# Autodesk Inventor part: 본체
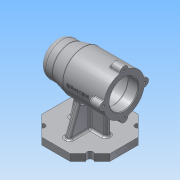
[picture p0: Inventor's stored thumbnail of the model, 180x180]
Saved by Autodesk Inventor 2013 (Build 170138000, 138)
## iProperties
Created: 2021-01
Part Number: 본체
Material: 알루미늄 6061
Document SubType Name: Modeling
Designer: Administrator
Density: 2.71 g/cm^3
Mass: 632.297 g
Surface Area: 613.785 cm^2
Volume: 233.32 cm^3
Author: Administrator
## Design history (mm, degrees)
sketch "스케치1" dims "d0" = 100
  geometry: L1 (20.711, 50)-(50, 20.711); L2 (50, 20.711)-(50, -20.711); L3 (50, -20.711)-(20.711, -50); L4 (20.711, -50)-(-20.711, -50); L5 (-20.711, -50)-(-50, -20.711); L6 (-50, -20.711)-(-50, 20.711); L7 (-50, 20.711)-(-20.711, 50); L8 (-20.711, 50)-(20.711, 50); 4 further points
  constraints: 16 end point, 2 coincident, 2 vertical alignment, 1 midpoint, 19 other
extrude "돌출1" new body sketch "스케치1" distance "d2" = 10; taper "d3" = 0 deg
sketch "스케치2"
  geometry: L1 (-50, -10)-(-20.711, -10) reference; L2 (20.711, 0)-(50, 0) reference; L3 (50, 65)-(-50, 65); L4 (-50, 65)-(-50, 90); L5 (-50, 90)-(-30, 90); L6 (-30, 90)-(-10, 95); L7 (-10, 95)-(50, 95); L8 (50, 95)-(50, 86); L9 (50, 86)-(35, 86); L10 (35, 86)-(35, 89); L11 (35, 89)-(-7, 89); L12 (-7, 89)-(-7, 86); L13 (-7, 86)-(-19, 86); L14 (-19, 86)-(-19, 82.5); L15 (-19, 82.5)-(-37, 82.5); L16 (-37, 82.5)-(-37, 81); L17 (-37, 81)-(-41, 81); L18 (-41, 81)-(-41, 75.5); L19 (-41, 75.5)-(-44, 75.5); L20 (-44, 75.5)-(-44, 65); 1 further point
  constraints: 36 end point, 14 parallel, 3 perpendicular, 1 point on line, 1 vertical alignment
  dimensions: "d5" = 75 distance between parallel lines of L3 L1; "d6" = 100 distance of L3.start L3.end; "d8" = 21 diameter of L19 L3; "d9" = 32 diameter of L17 L3; "d10" = 35 diameter of L15 L3; "d11" = 42 diameter of L13 L3; "d12" = 48 diameter of L11 L3; "d13" = 42 diameter of L9 L3; "d14" = 60 diameter of L7 L3; "d15" = 50 diameter of L5 L3; "d16" = 3 distance of L18.end L19.end; "d17" = 4 distance of L16.end L17.end; "d18" = 18 distance of L14.end L15.end; "d19" = 12 distance of L12.end L13.end; "d20" = 42 distance of L10.end L11.end; "d21" = 15 distance of L8.end L9.end; "d22" = 20 distance of L5.end L4.end; "d23" = 40 horizontal distance of L6.end L4.end; "d24" = 100 distance between parallel lines of L8 L4
revolve "회전1" sketch "스케치2" stored, may be unused: angle "d25" = 90 deg
sketch "스케치3"
  geometry: L1 (-20.711, 0)-(20.711, 0) reference; L2 (-50, 0)-(-20.711, 0) reference; L3 (20.711, 0)-(50, 0) reference; L4 (-50, 40)-(-30, 40) reference; L5 (-30, 40)-(-10, 35) reference; L6 (-10, 35)-(50, 35) reference; L7 (-27, 0)-(-19.225, 40); L8 (27, 35)-(27, 0); L9 (-19.225, 40)-(27, 40); L10 (27, 40)-(27, 35); 1 further point
  constraints: 8 end point, 4 point on line, 3 perpendicular
  dimensions: "d26" = 23 distance of L7.start L2.start; "d27" = 101 deg angle of L7 L2; "d28" = 23 distance of L3.end L8.end
extrude "돌출2" join sketch "스케치3" stored distance "d29" = 8; taper "d30" = 0 deg
sketch "스케치4"
  geometry: L1 (-50, 0)-(-20.711, 0) reference; L2 (-20.711, 0)-(-20.711, -10) reference; L3 (-50, -10)-(-20.711, -10) reference; L4 (-50, 0)-(-50, -10) reference; L5 (20.711, 0)-(50, 0) reference; L6 (-35, 0)-(-19.606, 42.293); L7 (19.606, 42.293)-(35, 0); A1 r 30 centre (0, 65) between (4, 35.268) and (-4, 35.268) reference; 1 further point
  constraints: 4 end point, 2 point on circle, 2 point on line
  dimensions: "d31" = 15 distance of L6.start L1.start; "d32" = 15 distance of L5.end L7.end; "d33" = 110 deg angle of L6 L1; "d34" = 110 deg angle of L5 L7
  node "투영된 루프1"
feature "리브1" dims "d35" = 1, "d36" = 8, "d37" = 0, "d38" = 0, "d39" = 1, "d40" = 1
feature "리브2" dims "d41" = 1, "d42" = 8, "d43" = 0, "d44" = 0, "d45" = 1, "d46" = 1
sketch "스케치5"
  geometry: C1 r 21 at (0, 0) reference; C2 r 6 at (0, -30); C3 r 6 at (30, 0); C4 r 6 at (0, 30); C5 r 6 at (-30, 0); A1 r 30 centre (0, 0) between (0, -30) and (30, 0) reference; 1 further point
  constraints: 4 centre point, 4 point on circle, 3 equal radius, 2 horizontal alignment, 2 vertical alignment
  dimensions: "d47" = 12 diameter of C2
extrude "돌출3" join sketch "스케치5" distance "d49" = 16; taper "d50" = 0 deg
sketch "스케치6"
  geometry: A1 r 6 centre (0, 0) between (-5.97, 0.6) and (5.97, 0.6) reference; A2 r 6 centre (30, 30) between (29.4, 24.03) and (29.4, 35.97) reference; A3 r 6 centre (0, 60) between (5.97, 59.4) and (-5.97, 59.4) reference; A4 r 6 centre (-30, 30) between (-29.4, 35.97) and (-29.4, 24.03) reference; 5 further points
  constraints: 4 coincident
hole "구멍1" sketch "스케치6" at (0, 60), (-30, 30), (0, 0), (30, 30) diameter "d51" = 3.242; stored, may be unused: countersink angle "d55" = 90 deg, drill point angle "d57" = 118 deg; dims "d52" = 8, "d53" = 4, "d54" = 2, "d56" = 10
sketch "스케치7"
  geometry: L1 (20.711, 50)-(50, 20.711) reference; L2 (-50, 20.711)-(-20.711, 50) reference; L3 (-20.711, -50)-(-50, -20.711) reference; L4 (50, -20.711)-(20.711, -50) reference; L5 (0, 0)-(-35.355, 35.355); L6 (0, 0)-(-35.355, -35.355); L7 (0, 0)-(35.355, -35.355); L8 (0, 0)-(35.355, 35.355); C1 r 4.5 at (-35.355, 35.355); C2 r 4.5 at (-35.355, -35.355); C3 r 4.5 at (35.355, -35.355); C4 r 4.5 at (35.355, 35.355)
  constraints: 8 end point, 4 centre point, 4 coincident, 4 midpoint, 3 equal radius
  dimensions: "d59" = 9 diameter of C1
extrude "돌출4" cut sketch "스케치7" distance "d61" = 10; taper "d62" = 0 deg
node "작업 평면1"
sketch "스케치8"
  geometry: L1 (50, 70.97)-(50, 94.4) reference; L2 (-50, 40)-(-50, 90) reference; 3 further points
  constraints: 1 horizontal alignment, 1 midpoint, 1 other
  dimensions: "d64" = 38 distance from line of L1 point (12, 65)
feature "엠보싱1" sketch "스케치8" dims "d5" = 75, "d6" = 100, "d8" = 21, "d9" = 32, "d10" = 35, "d11" = 42, "d12" = 48, "d13" = 42, "d14" = 60, "d15" = 50, "d16" = 3, "d17" = 4, "d18" = 18, "d19" = 12, "d20" = 42, "d21" = 15, "d22" = 20, "d23" = 40, "d24" = 100, "d65" = 0.5, "d66" = 0
fillet "모깎기1" dims "d67" = 10
fillet "모깎기2" dims "d68" = 3
fillet "모깎기3" dims "d69" = 1
fillet "모깎기4" dims "d70" = 0.3
fillet "모깎기5" dims "d71" = 3
fillet "모깎기6" dims "d72" = 3
chamfer "모따기1" distance "d73" = 1; stored, may be unused: second distance "d74" = 2, angle "d75" = 45 deg
fillet "모깎기7" dims "d76" = 3
fillet "모깎기8" dims "d77" = 3
fillet "모깎기9" dims "d78" = 3
fillet "모깎기10" dims "d79" = 3
fillet "모깎기11" dims "d80" = 3
node "솔리드1"
